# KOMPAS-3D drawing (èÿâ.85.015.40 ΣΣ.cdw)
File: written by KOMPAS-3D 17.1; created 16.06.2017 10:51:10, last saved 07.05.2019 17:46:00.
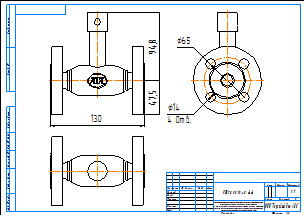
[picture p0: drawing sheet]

Sheet 1: A3, landscape

Title block, sheet 1: name: КШГ.85.015.40 фф; material: Внимание! Данный продукт является объектом авторского права ООО «Торговый Дом АДЛ». / Запрещается изменение, копирование, распространение / (в том числе путем копирования на другие сайты и ресурсы в Интернете) / или любое иное использование информации и объектов без предварительного / согласия правообладателя (ООО «Торговый Дом АДЛ»).; scale: 1:1; sheets: 1; organisation: ООО "Торговый дом АДЛ"; sheet format: A3; stored path: C:\Users\tra\Desktop\2д чертежи\Шаровые краны БИВАЛ\КШ_Бивал_серия_82_85\KOMPAS 2D\КШГ.85.015.40 фф.cdw

Views: Спереди 1, Проекционный вид 2, Проекционный вид 3
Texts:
  Klimkovich
  ADL
Dimensions and other numbers on the sheet: 130; 94,8; 47,5; 65; 14; 4 Отв.; 1:1; 1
